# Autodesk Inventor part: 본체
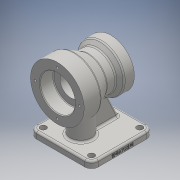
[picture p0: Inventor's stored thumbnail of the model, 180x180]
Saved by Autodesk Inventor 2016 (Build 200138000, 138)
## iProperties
Created: 2019-01
Part Number: 본체
Material: 일반
Document SubType Name: Modeling
Designer: USER
Density: 1 g/cm^3
Appearance: 기본값
Author: USER
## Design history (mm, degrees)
sketch "스케치1"
  geometry: L1 (-46, 46)-(46, 46); L2 (46, 46)-(46, -46); L3 (46, -46)-(-46, -46); L4 (-46, -46)-(-46, 46); 3 further points
  constraints: 8 end point, 2 midpoint, 2 parallel, 1 horizontal, 1 horizontal alignment, 1 perpendicular, 1 vertical alignment
  dimensions: "d0" = 92 distance of L2.end L3.end; "d1" = 92 distance of L1.end L2.end
extrude "돌출1" new body sketch "스케치1" distance "d2" = 10; taper "d3" = 0 deg
fillet "모깎기1" dims "d4" = 10
sketch "스케치2"
  geometry: L1 (-36, -46)-(36, -46) reference; L2 (46, -36)-(46, 36) reference; L3 (36, 46)-(-36, 46) reference; L4 (-46, 36)-(-46, -36) reference; A1 r 10 centre (-36, -36) between (-46, -36) and (-36, -46) reference; A2 r 10 centre (36, -36) between (36, -46) and (46, -36) reference; A3 r 10 centre (36, 36) between (46, 36) and (36, 46) reference; A4 r 10 centre (-36, 36) between (-36, 46) and (-46, 36) reference; 5 further points
  constraints: 4 coincident
hole "구멍1" sketch "스케치2" at (-36, 36), (36, 36), (36, -36), (-36, -36) diameter "d5" = 9; stored, may be unused: countersink angle "d9" = 90 deg, drill point angle "d11" = 118 deg; dims "d6" = 6, "d7" = 4, "d8" = 2, "d10" = 8
sketch "스케치3"
  geometry: L1 (-51, 80)-(29, 80); L2 (-46, 0)-(-46, 10) reference; L3 (-51, 120)-(-51, 106); L4 (-51, 106)-(-31, 106); L5 (-31, 106)-(-31, 96); L6 (-31, 96)-(12, 96); L7 (12, 96)-(12, 100); L8 (12, 100)-(29, 100); L9 (29, 100)-(29, 115); L10 (29, 115)-(14, 115); L11 (14, 115)-(8.126, 108); L12 (8.126, 108)-(-5.215, 108); L13 (-5.215, 108)-(-26, 120); L14 (-26, 120)-(-51, 120); 1 further point
  constraints: 27 end point, 7 perpendicular, 2 parallel, 1 horizontal, 1 vertical, 1 vertical alignment
  dimensions: "d12" = 5 distance from line of L2 L1.start; "d13" = 80 distance of L1.start L1.end; "d15" = 80 vertical distance of point (0, 0) L1.end; "d16" = 20 distance of L3.end L4.end; "d17" = 52 diameter of L4 L1; "d18" = 80 diameter of L14 L1; "d19" = 25 distance of L13.end L3.start; "d20" = 80 horizontal distance of L9.end L3.start; "d21" = 15 distance of L9.end L10.end; "d22" = 17 distance of L7.end L8.end; "d23" = 56 diameter of L12 L1; "d24" = 40 diameter of L8 L1; "d25" = 32 diameter of L6 L1; "d26" = 70 diameter of L10 L1; "d27" = 50 deg angle of L12 L11; "d28" = 30 deg angle of L12 L13
revolve "회전1" sketch "스케치3" stored, may be unused: angle "d29" = 90 deg
sketch "스케치4"
  geometry: L1 (36, -46)-(-36, -46) reference; C1 r 16 at (0, -16); 1 further point
  constraints: 1 centre point, 1 vertical alignment
  dimensions: "d30" = 32 diameter of C1; "d32" = 30 distance from line of L1 C1.centre
extrude "돌출2" join sketch "스케치4" stored distance "d33" = 10; taper "d34" = 0 deg
sketch "스케치5"
  geometry: L1 (36, 10)-(-36, 10) reference; L2 (36, 10)-(19.679, 45); L3 (14, 45)-(29, 45) reference; L4 (46, 10)-(46, 0) reference; 1 further point
  constraints: 2 end point, 2 point on line
  dimensions: "d35" = 10 distance from line of L4 L2.start; "d36" = 25 deg angle of L4 L2
feature "리브1" sketch "스케치5" dims "d37" = 1, "d38" = 10, "d39" = 0, "d40" = 0, "d41" = 1, "d42" = 1
sketch "스케치6"
  geometry: C1 r 40 at (0, 0) reference; C2 r 26 at (0, 0) reference; 2 further points
  constraints: 1 horizontal alignment
  dimensions: "d43" = 33 distance of C1.centre point (33, 0)
hole "구멍2" sketch "스케치6" at (33, 0) diameter "d44" = 3.242; stored, may be unused: countersink angle "d48" = 90 deg, drill point angle "d50" = 118 deg; dims "d45" = 9, "d46" = 4, "d47" = 2, "d49" = 11
sketch "스케치7"
  geometry: C1 r 20 at (0, 0) reference; C2 r 35 at (0, 0) reference; 2 further points
  constraints: 1 horizontal alignment
  dimensions: "d54" = 27.5 distance of C1.centre point (-27.5, 0)
hole "구멍3" sketch "스케치7" at (-27.5, 0) diameter "d55" = 3.242; stored, may be unused: countersink angle "d59" = 90 deg, drill point angle "d61" = 118 deg; dims "d56" = 9, "d57" = 4, "d58" = 2, "d60" = 11
fillet "모깎기2" dims "d65" = 1
fillet "모깎기3" dims "d66" = 0.6
chamfer "모따기1" distance "d67" = 1; stored, may be unused: second distance "d68" = 2, angle "d69" = 45 deg
fillet "모깎기4" dims "d70" = 3
fillet "모깎기5" dims "d71" = 3
fillet "모깎기6" dims "d72" = 3
sketch "스케치9"
  geometry: L1 (-7, -10)-(0, -10) reference; L2 (0, 72)-(0, 0) reference; 2 further points
  constraints: 1 other
  dimensions: "d73" = 46 distance from line of L1 point (-4, 36); "d74" = 4 distance from line of L2 point (-4, 36)
feature "엠보싱1" sketch "스케치9" dims "d0" = 92, "d1" = 92, "d75" = 0.5, "d76" = 0
node "솔리드1"
pattern_circular "원형 패턴1" dims angle "d52" = 360 deg
pattern_circular "원형 패턴2" dims angle "d63" = 360 deg
node "투영된 루프1"
node "투영된 루프2"
node "투영된 루프3"
